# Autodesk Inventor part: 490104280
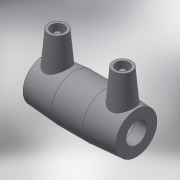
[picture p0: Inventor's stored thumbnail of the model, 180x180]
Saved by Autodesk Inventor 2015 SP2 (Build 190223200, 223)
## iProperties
Created: 2017-06
Part Number: 490104280
Material: Generic
Description: PLASSON COUPLER 280-280
Document SubType Name: Modeling
Designer: KIM
Mass: 55.0731 g
Surface Area: 148.067 cm^2
Volume: 55.0731 cm^3
Density: 1 g/cm^3
Appearance: Default
Author: KIM
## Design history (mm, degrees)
derived "490104.ipt"
feature "Solid1::490104.ipt"
tag "TaggingFeature1"
body "Solid1"
other parameters: "d0" = 275, "d2" = 342, "d3" = 134, "d4" = 91.66667, "d5" = 307.8, "d6" = 266, "d8" = 168 deg, "d10" = 53.6, "d11" = 17.86667, "d13" = 275, "d14" = 17.6296, "d15" = 134, "d16" = 134, "d17" = 266, "d19" = 3.52592, "d20" = 168 deg, "d22" = 321.48, "d23" = 342, "d24" = 311.8356, "d25" = 135 deg, "d26" = 151.25, "d27" = 135 deg, "d30" = 14, "d31" = 96.25, "d34" = 5 deg, "d35" = 15, "d39" = 5 deg, "d41" = 4, "d42" = 14, "d43" = 0, "d45" = 4, "d46" = 14, "d47" = 0, "d48" = 3, "d49" = 0, "d50" = 3, "d51" = 0, "d52" = 38.86, "d53" = 9.715, "L_" = 275, "L_1" = 134, "D_" = 342, "d_2" = 12
